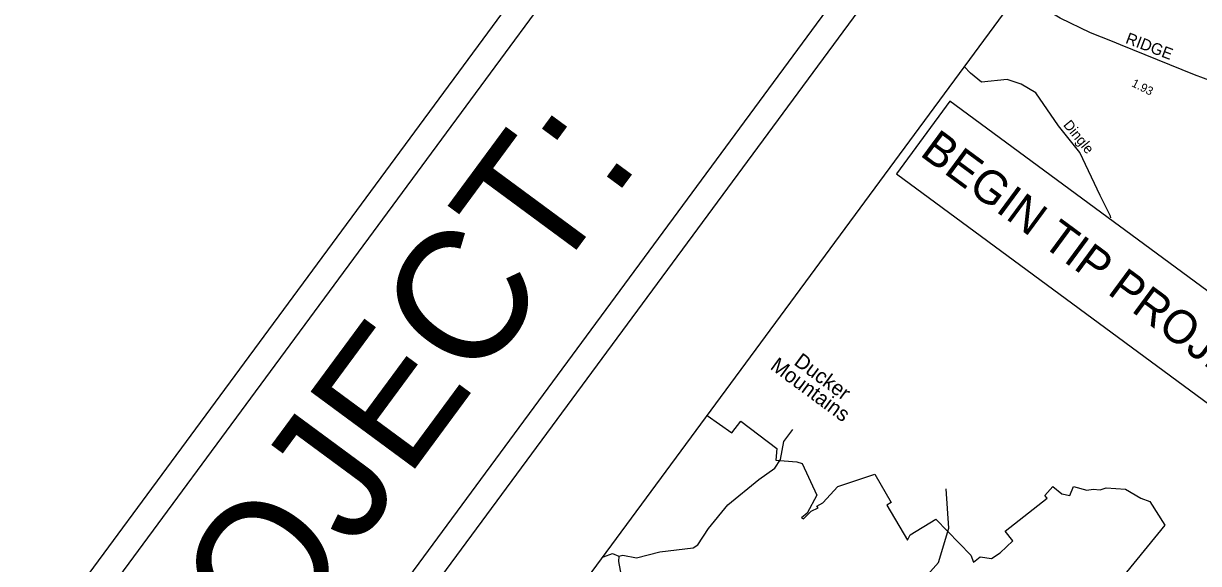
# Model space of a CAD drawing. Extents: x 945666 to 965748, y 644452 to 663300.
# Drawn here: x 951483 to 953745, y 659710 to 660750 of the extents above; entities that cross this region are included whole.
import ezdxf

# ---------------------------------------------------------------- set-up
doc = ezdxf.new("R2010")
doc.units = 0
for name, color, linetype in [('Exist Boundary Political City Limit New', 7, 'Continuous'), ('Exist Geographical Mountain Summit Label', 7, 'Continuous'), ('Exist Hydrographic Creek Single Shore', 7, 'Continuous'), ('Exist Road Blue Ridge Parkway', 7, 'Continuous'), ('Exist Road Blue Ridge Parkway Label', 7, 'Continuous'), ('Exist Road Secondary Mileage Tenths English Label', 7, 'Continuous'), ('Old_Level_1', 7, 'Continuous'), ('Old_Level_48', 7, 'Continuous'), ('Prop EOT', 7, 'Continuous'), ('Prop Paved Shoulder', 7, 'Continuous'), ('Sheet Title CELL', 7, 'Continuous')]:
    doc.layers.add(name, color=color, linetype=linetype)

msp = doc.modelspace()

# ---------------------------------------------------------------- linework, layer by layer
at = {"layer": 'Exist Boundary Political City Limit New'}
for points in [[(952798.9, 659995.4), (952846.8, 659962.2), (952864.1, 659984.4), (952933, 659931.8), (952931.6, 659909.2), (952971.5, 659906.1), (952982.2, 659902.9), (953010, 659841.9), (952991.7, 659807.5), (952980.8, 659798.5), (952984.5, 659796.2), (952999.6, 659811.4), (953013.1, 659817.6), (953010.2, 659820.7), (953021.8, 659827), (953050.4, 659858.6), (953122.1, 659882.4), (953153.2, 659827.9)], [(953153.2, 659827.9), (953145, 659822.7), (953184.5, 659755.6), (953189.7, 659765.6), (953239.2, 659795.9), (953306.8, 659726.4), (953311.8, 659712.8), (953324.5, 659723.1), (953346.6, 659720.3), (953363.3, 659730.8), (953387.7, 659754.1), (953372.9, 659772.7), (953453.7, 659836.4), (953449.4, 659841), (953464.7, 659858.5), (953482.2, 659844.3), (953497.5, 659841), (953504.3, 659858.6), (953529.7, 659851.7), (953542.5, 659853.7), (953555.9, 659852.4), (953567.2, 659855.7), (953604.7, 659853.5), (953633.7, 659836.2), (953651.5, 659829.6), (953680.1, 659783.9), (953606.2, 659694)]]:
    msp.add_lwpolyline(points, dxfattribs=at)
at = {"layer": 'Exist Hydrographic Creek Single Shore'}
for points in [[(953576.2, 660375.8), (953575.4, 660378.9), (953555.5, 660418.4), (953516.6, 660501.6), (953475.5, 660552.6), (953431.9, 660616.1), (953403.8, 660632.9), (953376.5, 660642.1), (953327, 660637.1), (953305.8, 660654), (953294, 660666.7)], [(952629.2, 659724.2), (952636.6, 659726.5), (952662.9, 659721.4), (952707.8, 659732.6), (952772.2, 659740.6), (952780.9, 659746.3), (952801.9, 659778), (952839.1, 659823), (952898.9, 659872.2), (952929.7, 659893.6), (952940.2, 659910.3), (952946.9, 659944.9), (952964.1, 659968.3)], [(952629.2, 659724.2), (952628.2, 659714.2), (952641.4, 659645.5), (952651.2, 659621.3), (952667, 659597.8), (952705.6, 659569.7), (952737.7, 659559.6), (952816.4, 659570), (952829.5, 659563.8), (952898.1, 659511), (952923.4, 659504.4), (952953.2, 659507.3), (953006.8, 659531.1), (953060.5, 659544.7), (953084.3, 659553.9), (953110.4, 659574.6), (953144.9, 659595.4), (953190.4, 659656.1), (953207.9, 659671.2), (953244.7, 659712.2), (953264.1, 659778.5), (953259.3, 659854.2)], [(952598.4, 659723.4), (952599.5, 659723.4), (952617.1, 659729.8), (952629.2, 659724.2)]]:
    msp.add_lwpolyline(points, dxfattribs=at)
at = {"layer": 'Exist Road Blue Ridge Parkway'}
for points in [[(953737.3, 660650.8), (953689.8, 660669.9), (953594.7, 660708.8), (953579.2, 660715), (953537.2, 660731.6), (953478.8, 660759.9), (953428.2, 660790.5), (953405.4, 660804.3), (953398.4, 660808.2)], [(953903.8, 660582.4), (953869.3, 660599.6), (953771.7, 660638.2), (953737.3, 660650.8)]]:
    msp.add_lwpolyline(points, dxfattribs=at)
at = {"layer": 'Old_Level_1'}
msp.add_lwpolyline([(953667.4, 661172.9), (956829.7, 658840.6), (955088.6, 656479.8), (951926.2, 658812.1)], close=True, dxfattribs=at)
at = {"layer": 'Prop EOT'}
msp.add_lwpolyline([(954233.6, 659887.2), (953266.5, 660600.4), (953163.3, 660460.5), (954130.3, 659747.3)], close=True, dxfattribs=at)
at = {"layer": 'Sheet Title CELL'}
for p, q in [((947649.9, 653481.5), (953704.1, 661690.4)), ((948788.2, 654940.7), (953744.3, 661660.7))]:
    msp.add_line(p, q, dxfattribs=at)
for points in [[(953331.4, 662027.4), (947217.8, 653738)], [(953331.4, 662027.4), (947217.8, 653738)], [(953342, 661957.4), (947287.8, 653748.6)]]:
    msp.add_lwpolyline(points, dxfattribs=at)

# ---------------------------------------------------------------- texts
at = {"layer": 'Exist Geographical Mountain Summit Label'}
for s, p in [('Mountains', (952918.7, 660086.1)), ('Ducker', (952964.3, 660094.5))]:
    msp.add_text(s, height=28.58, rotation=323.5908, dxfattribs=at).set_placement(p)
at = {"layer": 'Exist Road Blue Ridge Parkway Label'}
msp.add_text('RIDGE', height=22.08, rotation=339.2694, dxfattribs=at).set_placement((953602.9, 660712.5))
at = {"layer": 'Exist Road Secondary Mileage Tenths English Label'}
msp.add_text('1.93', height=16.24, rotation=333.3496, dxfattribs=at).set_placement((953614.8, 660629.6))
at = {"layer": 'Old_Level_48'}
msp.add_text('BEGIN TIP PROJECT U-5834', height=64.231, rotation=323.5908, dxfattribs=at).set_placement((953206.5, 660497))
at = {"layer": 'Prop Paved Shoulder'}
msp.add_text('Dingle', height=19.49, rotation=309.3783, dxfattribs=at).set_placement((953483.6, 660554.1))
at = {"layer": 'Sheet Title CELL'}
msp.add_text('TIP PROJECT:', height=250, rotation=53.5908, dxfattribs=at).set_placement((951327.6, 658659.9))

doc.saveas('drawing.dxf')
